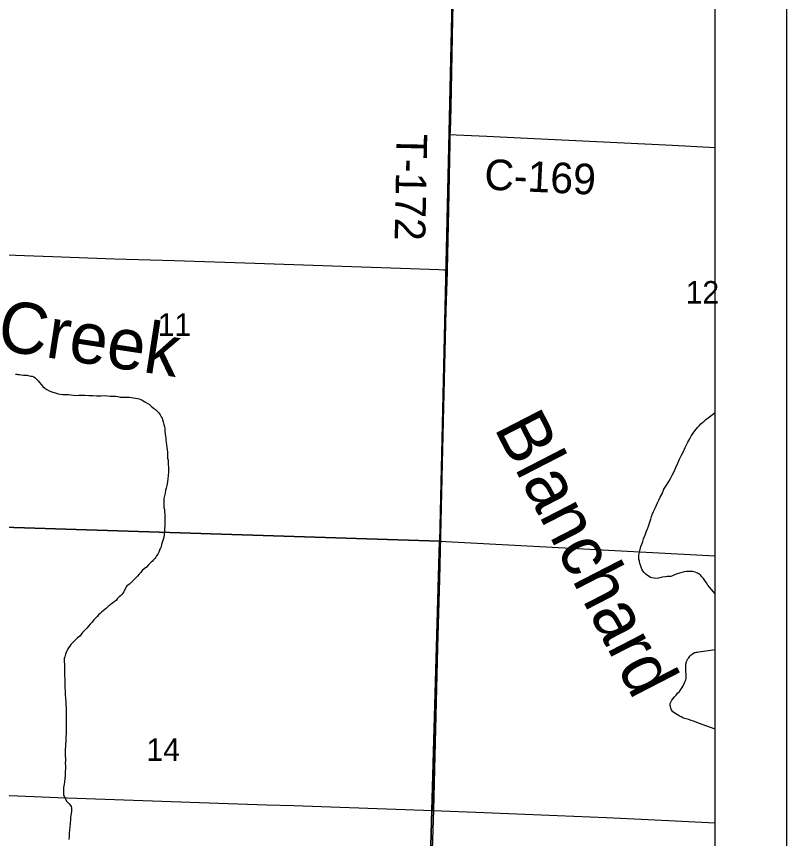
# Model space of a CAD drawing. Extents: x 0 to 68, y 0 to 52.9.
# Drawn here: x 30.122 to 31.501, y 15.342 to 16.814 of the extents above; entities that cross this region are included whole.
import ezdxf

# ---------------------------------------------------------------- set-up
doc = ezdxf.new("R2010")
doc.units = 0
for name, color, linetype in [('Default', 7, 'Continuous'), ('GM_X_County_Road', 7, 'Continuous'), ('GM_X_County_Road_Text', 7, 'Continuous'), ('GM_X_Minor_River', 7, 'Continuous'), ('GM_X_Minor_River_Text', 7, 'Continuous'), ('GM_X_Township', 7, 'Continuous'), ('GM_X_Township_Road', 7, 'Continuous'), ('GM_X_Township_Road_Text', 7, 'Continuous'), ('SH_Data', 7, 'Continuous')]:
    doc.layers.add(name, color=color, linetype=linetype)

msp = doc.modelspace()

# ---------------------------------------------------------------- linework, layer by layer
at = {"layer": 'Default'}
msp.add_line((31.3735, 14.1085), (31.3735, 20.8614), dxfattribs=at)
for points in [[(29.9405, 16.874), (30.9018, 16.8419), (30.8795, 15.8743), (29.9124, 15.9054)], [(29.9124, 15.9054), (30.8795, 15.8743), (30.8525, 14.9101), (29.8898, 14.9418)]]:
    msp.add_lwpolyline(points, close=True, dxfattribs=at)
for points in [[(31.348, 16.0843), (31.3509, 16.0872), (31.3539, 16.0894), (31.3568, 16.0923), (31.3612, 16.0953), (31.3735, 16.1048)], [(31.3735, 15.7803), (31.3605, 15.7957), (31.3579, 15.8001), (31.355, 15.8042), (31.3525, 15.8075), (31.3499, 15.8108), (31.3477, 15.813), (31.3448, 15.8156), (31.343, 15.8167), (31.3408, 15.8178), (31.3378, 15.8189), (31.3334, 15.82), (31.3298, 15.8204), (31.3257, 15.8204), (31.3221, 15.8204), (31.318, 15.8197), (31.314, 15.8183), (31.3096, 15.8172), (31.3052, 15.8157), (31.3008, 15.8139), (31.2971, 15.8124), (31.2942, 15.8114), (31.2916, 15.811), (31.2876, 15.811), (31.2843, 15.8107), (31.2795, 15.8099), (31.2747, 15.8088), (31.2696, 15.8078), (31.2645, 15.8081), (31.2604, 15.8089), (31.2575, 15.8096), (31.2553, 15.8111), (31.2524, 15.813), (31.2494, 15.8152), (31.2462, 15.8185), (31.244, 15.8214), (31.2421, 15.8244), (31.2407, 15.8277), (31.2396, 15.8313), (31.2385, 15.8346), (31.2378, 15.8387), (31.237, 15.8423), (31.2367, 15.8456), (31.2371, 15.8489), (31.2374, 15.8522), (31.2404, 15.8647), (31.2419, 15.8691), (31.2437, 15.8738), (31.2452, 15.8786), (31.247, 15.883), (31.2485, 15.887), (31.25, 15.8914), (31.2522, 15.8965), (31.254, 15.9013), (31.2559, 15.9064), (31.2581, 15.9138), (31.2596, 15.9185), (31.2611, 15.9233), (31.2629, 15.9277), (31.2648, 15.9313), (31.2666, 15.9346), (31.2684, 15.9387), (31.2703, 15.943), (31.2725, 15.9478), (31.2751, 15.9533), (31.2784, 15.9591), (31.2817, 15.9676), (31.2865, 15.9745), (31.2905, 15.9811), (31.2938, 15.9866), (31.2968, 15.9928), (31.3001, 15.9994), (31.3031, 16.0064), (31.3064, 16.0141), (31.3097, 16.0214), (31.3134, 16.0283), (31.3171, 16.0349), (31.32, 16.0422), (31.3248, 16.0514), (31.3281, 16.0576), (31.3311, 16.0635), (31.3344, 16.0679), (31.337, 16.0719), (31.3395, 16.0752), (31.3421, 16.0781), (31.345, 16.081), (31.348, 16.0843)], [(31.3735, 14.8819), (30.8525, 14.9101), (30.8795, 15.8743), (31.3735, 15.8482)], [(31.3735, 15.5378), (31.3438, 15.5487), (31.3394, 15.5505), (31.335, 15.5524), (31.3306, 15.5535), (31.3266, 15.555), (31.3218, 15.5561), (31.3189, 15.5568), (31.3156, 15.5583), (31.3126, 15.5598), (31.3093, 15.5616), (31.306, 15.5635), (31.3031, 15.5653), (31.3006, 15.5672), (31.298, 15.569), (31.2954, 15.5723), (31.2943, 15.5756), (31.2936, 15.5782), (31.2929, 15.5804), (31.2929, 15.5837), (31.2947, 15.5873), (31.2962, 15.5899), (31.2984, 15.5928), (31.301, 15.5958), (31.3036, 15.5987), (31.3058, 15.6023), (31.3094, 15.6053), (31.312, 15.6086), (31.3146, 15.6122), (31.3161, 15.6151), (31.3175, 15.6177), (31.3187, 15.621), (31.3201, 15.6239), (31.3209, 15.6261), (31.3216, 15.6287), (31.3216, 15.6324), (31.3213, 15.6441), (31.3213, 15.6474), (31.3209, 15.65), (31.3213, 15.6522), (31.3213, 15.654), (31.3217, 15.6562), (31.3224, 15.6591), (31.3235, 15.6613), (31.3243, 15.6635), (31.3261, 15.6657), (31.3279, 15.6686), (31.3305, 15.6708), (31.3323, 15.6723), (31.3345, 15.6737), (31.3364, 15.6748), (31.3382, 15.6752), (31.3404, 15.6756), (31.3422, 15.6755), (31.3441, 15.6763), (31.3735, 15.6804)]]:
    msp.add_lwpolyline(points, dxfattribs=at)
at = {"layer": 'GM_X_County_Road'}
for points in [[(30.9052, 17.0249), (30.9068, 17.0213), (30.9077, 17.0167), (30.9078, 17.0076), (30.9057, 16.9327), (30.9031, 16.8098), (30.8998, 16.6509), (30.8986, 16.6072), (30.8985, 16.6028)], [(30.8985, 16.6028), (30.9097, 16.6019), (30.9647, 16.5995), (31.0246, 16.5965), (31.2972, 16.5832), (31.3735, 16.5791)]]:
    msp.add_lwpolyline(points, dxfattribs=at)
at = {"layer": 'GM_X_Minor_River'}
for points in [[(30.1202, 16.1737), (30.1224, 16.1733), (30.1246, 16.173), (30.1275, 16.1726), (30.1304, 16.1722), (30.1348, 16.1718), (30.1378, 16.1718), (30.1411, 16.1714), (30.1429, 16.1711), (30.1451, 16.1707), (30.1477, 16.17), (30.1499, 16.1696), (30.1528, 16.1685), (30.1553, 16.1666), (30.1583, 16.1641), (30.1608, 16.1615), (30.1634, 16.1585), (30.166, 16.1552), (30.1692, 16.1516), (30.1725, 16.1483), (30.1762, 16.1457), (30.1806, 16.1438), (30.1854, 16.1416), (30.1912, 16.1398), (30.1964, 16.1383), (30.2004, 16.1375), (30.2048, 16.1371), (30.2081, 16.1371), (30.2114, 16.1371), (30.2151, 16.1371), (30.2194, 16.1364), (30.2238, 16.1356), (30.2286, 16.1352), (30.2334, 16.1356), (30.237, 16.1359), (30.2407, 16.1359), (30.2444, 16.1359), (30.2513, 16.1355), (30.2587, 16.1351), (30.2656, 16.1348), (30.273, 16.1347), (30.2799, 16.1351), (30.2851, 16.1347), (30.2895, 16.1343), (30.2997, 16.1339), (30.3034, 16.1332), (30.3078, 16.1324), (30.3129, 16.132), (30.3166, 16.132), (30.3203, 16.132), (30.3239, 16.132), (30.328, 16.1316), (30.3316, 16.1312), (30.3353, 16.1305), (30.3386, 16.1297), (30.3419, 16.129), (30.3445, 16.1279), (30.3474, 16.1268), (30.3518, 16.1242)], [(30.3518, 16.1242), (30.3562, 16.1216), (30.3602, 16.119), (30.3635, 16.1161), (30.3675, 16.1128), (30.3708, 16.1102), (30.3741, 16.1073), (30.3767, 16.104), (30.3792, 16.1007), (30.3814, 16.0973), (30.3829, 16.0948), (30.3836, 16.0915), (30.3847, 16.0882), (30.3858, 16.0834), (30.3869, 16.079), (30.3876, 16.0768), (30.3876, 16.0742), (30.388, 16.0709), (30.3883, 16.0665), (30.3887, 16.0625), (30.3894, 16.0588), (30.3898, 16.0555), (30.3901, 16.0519), (30.3909, 16.0467), (30.3912, 16.042), (30.3919, 16.0379), (30.3923, 16.0343), (30.3923, 16.0302), (30.3926, 16.0262), (30.3926, 16.0233), (30.3934, 16.0196), (30.3937, 16.0148), (30.3937, 16.0111), (30.3941, 16.0075), (30.394, 16.0023), (30.394, 15.998), (30.3933, 15.9862), (30.3925, 15.9804), (30.3914, 15.9741), (30.3903, 15.9694), (30.3892, 15.9653), (30.3881, 15.9606), (30.387, 15.9554), (30.3862, 15.9507), (30.3858, 15.9452), (30.3858, 15.94), (30.3862, 15.9349), (30.3869, 15.9312), (30.3873, 15.9272), (30.3876, 15.9228), (30.388, 15.9188), (30.388, 15.9147), (30.388, 15.91), (30.3876, 15.9052), (30.3876, 15.9012), (30.3872, 15.8968), (30.3872, 15.8924), (30.3868, 15.8887), (30.3864, 15.8858), (30.3857, 15.8818), (30.3846, 15.8774), (30.3838, 15.8741), (30.3831, 15.8719), (30.382, 15.8686), (30.3809, 15.8642), (30.3798, 15.8616), (30.3787, 15.8598), (30.3768, 15.855), (30.3754, 15.8514), (30.3728, 15.8484), (30.3717, 15.8459), (30.3695, 15.8433), (30.3673, 15.8411), (30.3654, 15.8389), (30.3632, 15.8371), (30.361, 15.8345), (30.3577, 15.8316), (30.3548, 15.828), (30.3507, 15.8247), (30.3474, 15.8218), (30.3445, 15.8185), (30.3415, 15.8152), (30.3386, 15.8119), (30.336, 15.809), (30.3338, 15.8068), (30.3265, 15.7995), (30.3243, 15.7976), (30.3217, 15.7954), (30.3199, 15.7944), (30.3184, 15.7925), (30.314, 15.7834), (30.3125, 15.7812), (30.3107, 15.779), (30.3084, 15.7768), (30.3062, 15.7746), (30.3044, 15.7728), (30.3026, 15.7709), (30.3004, 15.768), (30.2967, 15.7658), (30.2941, 15.7636), (30.2912, 15.7618)], [(30.2912, 15.7618), (30.289, 15.76), (30.2864, 15.7574), (30.2835, 15.7545), (30.2805, 15.7523), (30.2772, 15.7498), (30.2743, 15.7472), (30.2717, 15.745), (30.2691, 15.7428), (30.2662, 15.7395), (30.2636, 15.7366), (30.2607, 15.7333), (30.2574, 15.7293), (30.2541, 15.7256), (30.2511, 15.7224), (30.2482, 15.7187), (30.2452, 15.7158), (30.2427, 15.7132), (30.2401, 15.711), (30.2383, 15.7085), (30.2357, 15.7044), (30.2313, 15.7015), (30.228, 15.6982), (30.2247, 15.6946), (30.2217, 15.6916), (30.2191, 15.6891), (30.2173, 15.6865), (30.2151, 15.6836), (30.2136, 15.6807), (30.2121, 15.6781), (30.2107, 15.6748), (30.2096, 15.6719), (30.2085, 15.6671), (30.2073, 15.6642), (30.2073, 15.6613), (30.2073, 15.658), (30.2077, 15.655), (30.2077, 15.6521), (30.2077, 15.6495), (30.2077, 15.6459), (30.208, 15.6334), (30.2084, 15.6275), (30.2087, 15.6228), (30.2087, 15.6173), (30.2087, 15.6118), (30.209, 15.6059), (30.2094, 15.5993), (30.2097, 15.5931), (30.2101, 15.5868), (30.2105, 15.5813), (30.2108, 15.5758), (30.2112, 15.5711), (30.2112, 15.5674), (30.2111, 15.5612), (30.2108, 15.5553), (30.2107, 15.5505), (30.2107, 15.5447), (30.2107, 15.5366), (30.2107, 15.5293), (30.2103, 15.5238), (30.2103, 15.5201), (30.2103, 15.5157), (30.2099, 15.5106), (30.2095, 15.5065), (30.2092, 15.5022), (30.2092, 15.4978), (30.2091, 15.493), (30.2091, 15.489), (30.2095, 15.4857), (30.2095, 15.4816), (30.2091, 15.4765), (30.2095, 15.4721), (30.2095, 15.4673), (30.2091, 15.4615), (30.2091, 15.4574), (30.2094, 15.4552), (30.209, 15.4523), (30.2087, 15.4505), (30.2083, 15.4475), (30.2079, 15.4453), (30.2079, 15.4431), (30.2072, 15.4391), (30.2068, 15.4362), (30.2064, 15.4336), (30.2064, 15.4303), (30.2064, 15.4266), (30.2064, 15.4241), (30.2064, 15.4222), (30.2064, 15.4197), (30.2071, 15.4178), (30.2093, 15.4138), (30.2122, 15.4083), (30.2166, 15.4039), (30.2188, 15.4009), (30.2199, 15.3991), (30.2203, 15.3969), (30.2203, 15.394), (30.2203, 15.391), (30.2199, 15.387), (30.2192, 15.3837), (30.2188, 15.3797)], [(30.2188, 15.3797), (30.2188, 15.3753), (30.218, 15.3694), (30.2173, 15.3624), (30.2169, 15.3573), (30.2165, 15.3518), (30.2161, 15.3463), (30.2158, 15.3401)]]:
    msp.add_lwpolyline(points, dxfattribs=at)
at = {"layer": 'GM_X_Township'}
msp.add_lwpolyline([(27.3046, 17.882), (28.0252, 17.8646), (28.0383, 17.8644), (28.5162, 17.8494), (28.9971, 17.8406), (29.642, 17.8239), (29.9734, 17.8135), (30.4577, 17.7952), (30.9331, 17.7779), (30.9135, 17.1991), (30.9077, 17.017), (30.8985, 16.6023), (30.8927, 16.3623), (30.8688, 15.3927), (30.8528, 14.9106), (30.8428, 14.4289), (30.8361, 14.1085)], dxfattribs=at)
at = {"layer": 'GM_X_Township_Road'}
for points in [[(30.8985, 16.6028), (30.898, 16.5877), (30.8957, 16.4676), (30.8933, 16.3601)], [(29.9269, 16.3929), (29.9497, 16.3924), (30.0696, 16.3882), (30.1865, 16.3842), (30.2974, 16.3802), (30.4053, 16.3767), (30.5491, 16.372), (30.8098, 16.3632), (30.8788, 16.3608), (30.8877, 16.3604), (30.8933, 16.3601)], [(30.8933, 16.3601), (30.8932, 16.3568), (30.8911, 16.2879), (30.8852, 16.0393), (30.8833, 15.9615), (30.8797, 15.8058), (30.875, 15.6441), (30.868, 15.3986), (30.8678, 15.392)], [(29.9015, 15.4265), (30.0078, 15.4229), (30.1962, 15.4153), (30.4838, 15.4055), (30.5707, 15.4024), (30.6186, 15.4009), (30.8678, 15.392)], [(30.8678, 15.392), (30.9451, 15.3893), (31.1787, 15.3797), (31.2536, 15.3761), (31.3139, 15.3728), (31.3735, 15.37)]]:
    msp.add_lwpolyline(points, dxfattribs=at)
at = {"layer": 'SH_Data'}
msp.add_line((31.5015, 21), (31.5015, 14), dxfattribs=at)

# ---------------------------------------------------------------- texts
at = {"layer": 'Default'}
for s, height, rotation, p in [('12', 0.04038, 0, (31.3206, 16.2998)), ('11', 0.04038, 0, (30.3749, 16.242)), ('Blanchard', 0.09139, 297.2314, (30.9767, 16.0773)), ('14', 0.04038, 0, (30.3548, 15.481))]:
    msp.add_text(s, height=height, rotation=rotation, dxfattribs=at).set_placement(p)
at = {"layer": 'GM_X_County_Road_Text'}
msp.add_text('C-169', height=0.05481, rotation=357.2483, dxfattribs=at).set_placement((30.9592, 16.5042))
at = {"layer": 'GM_X_Minor_River_Text'}
msp.add_text('Creek', height=0.09139, rotation=351.3025, dxfattribs=at).set_placement((30.0848, 16.2175))
at = {"layer": 'GM_X_Township_Road_Text'}
msp.add_text('T-172', height=0.05481, rotation=268.8773, dxfattribs=at).set_placement((30.8031, 16.6044))

doc.saveas('drawing.dxf')
